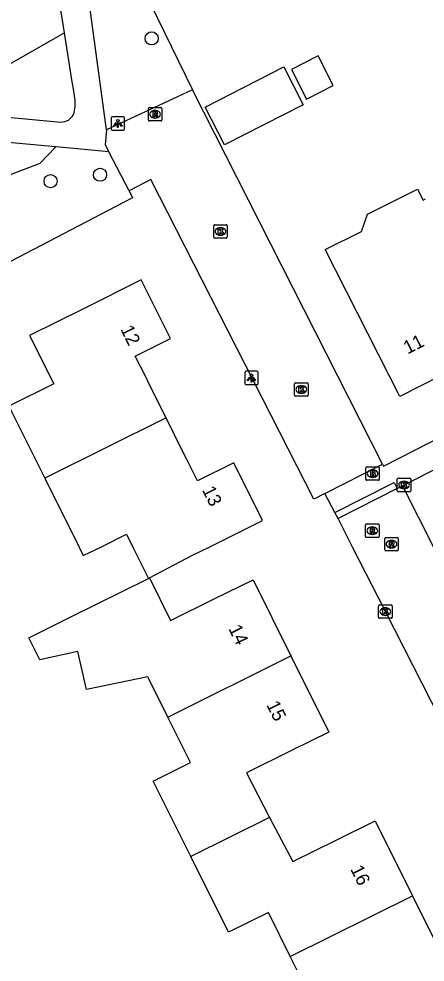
# Model space of a CAD drawing. Extents: x 162722 to 165099, y 384721 to 386283.
# Drawn here: x 163730.3 to 163760.6, y 384969 to 385039.4 of the extents above; entities that cross this region are included whole.
import ezdxf

# ---------------------------------------------------------------- set-up
doc = ezdxf.new("R2010")
doc.units = 0
for name, color, linetype in [('IMGEO_Boom', 7, 'Continuous'), ('IMGEO_Brandkraan', 7, 'Continuous'), ('IMGEO_Groenvoorziening', 7, 'Continuous'), ('IMGEO_Kolk', 7, 'Continuous'), ('IMGEO_Lichtpunt', 7, 'Continuous'), ('IMGEO_Pand', 7, 'Continuous'), ('IMGEO_Pand_nummerreeks', 7, 'Continuous'), ('IMGEO_Rijbaan_lokaal_open', 7, 'Continuous'), ('IMGEO_Rioolput', 7, 'Continuous'), ('IMGEO_Voetpad_open', 7, 'Continuous')]:
    doc.layers.add(name, color=color, linetype=linetype)

msp = doc.modelspace()

# ---------------------------------------------------------------- linework, layer by layer
at = {"layer": 'IMGEO_Boom'}
for centre in [(163740.246, 385037.942), (163736.396, 385027.77), (163732.709, 385027.289)]:
    msp.add_circle(centre, 0.489, dxfattribs=at)
at = {"layer": 'IMGEO_Brandkraan'}
for p, q in [((163756.215, 385005.051), (163756.215, 385005.903)), ((163756.29, 385005.977), (163757.142, 385005.977)), ((163756.703, 385005.757), (163756.728, 385005.757)), ((163757.216, 385005.903), (163757.216, 385005.051)), ((163757.142, 385004.977), (163756.29, 385004.977)), ((163756.726, 385005.197), (163756.701, 385005.197))]:
    msp.add_line(p, q, dxfattribs=at)
for points in [[(163756.215, 385005.051), (163756.215, 385005.903)], [(163756.29, 385005.977), (163757.142, 385005.977)], [(163756.563, 385005.677), (163756.563, 385005.277), (163756.776, 385005.277)], [(163756.794, 385005.677), (163756.563, 385005.677)], [(163757.216, 385005.903), (163757.216, 385005.051)], [(163757.142, 385004.977), (163756.29, 385004.977)], [(163756.742, 385005.596), (163756.688, 385005.596), (163756.688, 385005.52)], [(163756.688, 385005.52), (163756.741, 385005.52)], [(163756.75, 385005.444), (163756.688, 385005.444), (163756.688, 385005.363)], [(163756.688, 385005.363), (163756.75, 385005.363)]]:
    msp.add_lwpolyline(points, dxfattribs=at)
for centre, radius, start, end in [((163756.292, 385005.901), 0.0765, 91.55205, 178.44795), ((163756.292, 385005.901), 0.0765, 91.55205, 178.44795), ((163756.798, 385005.532), 0.145, 59.4692, 91.53667), ((163756.823, 385005.579), 0.0922, 285.51372, 58.15012), ((163757.14, 385005.901), 0.0765, 1.55205, 88.44795), ((163757.14, 385005.901), 0.0765, 1.55205, 88.44795), ((163756.292, 385005.053), 0.0765, 181.55205, 268.44795), ((163756.292, 385005.053), 0.0765, 181.55205, 268.44795), ((163756.743, 385005.558), 0.0379, 267.82845, 90.93552), ((163756.751, 385005.403), 0.0404, 269.87594, 90.50774), ((163756.782, 385005.528), 0.251, 268.66757, 293.53466), ((163756.828, 385005.387), 0.105, 301.31148, 78.98903), ((163757.14, 385005.053), 0.0765, 271.55205, 358.44795), ((163757.14, 385005.053), 0.0765, 271.55205, 358.44795)]:
    msp.add_arc(centre, radius, start, end, dxfattribs=at)
for centre, major_axis, ratio, start_param, end_param in [((163756.702, 385005.477), (-0.387, 0.002), 0.722429, 4.712389, 7.853982), ((163756.727, 385005.477), (-0.39, 0.002), 0.717154, 1.570796, 4.712389)]:
    msp.add_ellipse(centre, major_axis=major_axis, ratio=ratio, start_param=start_param, end_param=end_param, dxfattribs=at)
at = {"layer": 'IMGEO_Groenvoorziening'}
for points in [[(163738.045, 385044.879), (163743.285, 385034.094)], [(163733.752, 385038.348), (163723.683, 385032.609)], [(163715.637, 385026.452), (163717.423, 385023.192), (163721.071, 385022.027), (163726.195, 385024.046), (163728.214, 385027.228), (163731.94, 385028.626), (163733.096, 385029.842)], [(163738.567, 385026.557), (163738.822, 385026.058), (163738.155, 385025.71), (163714.087, 385013.147), (163707.49, 385026.219)]]:
    msp.add_lwpolyline(points, dxfattribs=at)
at = {"layer": 'IMGEO_Kolk'}
for p, q in [((163744.878, 385023.117), (163744.878, 385023.969)), ((163744.953, 385024.043), (163745.805, 385024.043)), ((163745.879, 385023.969), (163745.879, 385023.117)), ((163745.389, 385023.263), (163745.364, 385023.263)), ((163745.366, 385023.823), (163745.391, 385023.823)), ((163745.805, 385023.043), (163744.953, 385023.043)), ((163750.902, 385011.328), (163750.902, 385012.18)), ((163750.977, 385012.254), (163751.829, 385012.254)), ((163751.39, 385012.034), (163751.415, 385012.034)), ((163751.903, 385012.18), (163751.903, 385011.328)), ((163751.413, 385011.474), (163751.388, 385011.474)), ((163751.829, 385011.254), (163750.977, 385011.254)), ((163758.56, 385004.202), (163758.56, 385005.054)), ((163758.635, 385005.128), (163759.487, 385005.128)), ((163759.561, 385005.054), (163759.561, 385004.202)), ((163759.071, 385004.348), (163759.046, 385004.348)), ((163759.048, 385004.908), (163759.073, 385004.908)), ((163759.487, 385004.128), (163758.635, 385004.128)), ((163757.168, 384994.756), (163757.168, 384995.608)), ((163757.243, 384995.682), (163758.095, 384995.682)), ((163757.656, 384995.462), (163757.681, 384995.462)), ((163758.169, 384995.608), (163758.169, 384994.756)), ((163758.095, 384994.682), (163757.243, 384994.682)), ((163757.679, 384994.902), (163757.654, 384994.902))]:
    msp.add_line(p, q, dxfattribs=at)
for points in [[(163744.878, 385023.117), (163744.878, 385023.969)], [(163744.953, 385024.043), (163745.805, 385024.043)], [(163745.879, 385023.969), (163745.879, 385023.117)], [(163745.199, 385023.743), (163745.322, 385023.743), (163745.322, 385023.592), (163745.452, 385023.743), (163745.616, 385023.743), (163745.47, 385023.592), (163745.623, 385023.343), (163745.471, 385023.343), (163745.386, 385023.507), (163745.322, 385023.44), (163745.322, 385023.343), (163745.199, 385023.343), (163745.199, 385023.743)], [(163745.805, 385023.043), (163744.953, 385023.043)], [(163750.902, 385011.328), (163750.902, 385012.18)], [(163750.977, 385012.254), (163751.829, 385012.254)], [(163751.903, 385012.18), (163751.903, 385011.328)], [(163751.223, 385011.954), (163751.346, 385011.954), (163751.346, 385011.803), (163751.476, 385011.954), (163751.64, 385011.954), (163751.494, 385011.803), (163751.647, 385011.554), (163751.495, 385011.554), (163751.41, 385011.718), (163751.346, 385011.651), (163751.346, 385011.554), (163751.223, 385011.554), (163751.223, 385011.954)], [(163751.829, 385011.254), (163750.977, 385011.254)], [(163758.56, 385004.202), (163758.56, 385005.054)], [(163758.635, 385005.128), (163759.487, 385005.128)], [(163759.561, 385005.054), (163759.561, 385004.202)], [(163758.881, 385004.828), (163759.004, 385004.828), (163759.004, 385004.677), (163759.134, 385004.828), (163759.298, 385004.828), (163759.152, 385004.677), (163759.305, 385004.428), (163759.153, 385004.428), (163759.068, 385004.592), (163759.004, 385004.525), (163759.004, 385004.428), (163758.881, 385004.428), (163758.881, 385004.828)], [(163759.487, 385004.128), (163758.635, 385004.128)], [(163757.168, 384994.756), (163757.168, 384995.608)], [(163757.243, 384995.682), (163758.095, 384995.682)], [(163757.489, 384995.382), (163757.612, 384995.382), (163757.612, 384995.231), (163757.742, 384995.382), (163757.906, 384995.382), (163757.76, 384995.231), (163757.913, 384994.982), (163757.761, 384994.982), (163757.676, 384995.146), (163757.612, 384995.079), (163757.612, 384994.982), (163757.489, 384994.982), (163757.489, 384995.382)], [(163758.169, 384995.608), (163758.169, 384994.756)], [(163758.095, 384994.682), (163757.243, 384994.682)]]:
    msp.add_lwpolyline(points, dxfattribs=at)
for centre, start, end in [((163744.955, 385023.967), 91.55205, 178.44795), ((163744.955, 385023.967), 91.55205, 178.44795), ((163745.803, 385023.967), 1.55205, 88.44795), ((163745.803, 385023.967), 1.55205, 88.44795), ((163744.955, 385023.119), 181.55205, 268.44795), ((163744.955, 385023.119), 181.55205, 268.44795), ((163745.803, 385023.119), 271.55205, 358.44795), ((163745.803, 385023.119), 271.55205, 358.44795), ((163750.979, 385012.178), 91.55205, 178.44795), ((163750.979, 385012.178), 91.55205, 178.44795), ((163751.827, 385012.178), 1.55205, 88.44795), ((163751.827, 385012.178), 1.55205, 88.44795), ((163750.979, 385011.33), 181.55205, 268.44795), ((163750.979, 385011.33), 181.55205, 268.44795), ((163751.827, 385011.33), 271.55205, 358.44795), ((163751.827, 385011.33), 271.55205, 358.44795), ((163758.637, 385005.052), 91.55205, 178.44795), ((163758.637, 385005.052), 91.55205, 178.44795), ((163759.485, 385005.052), 1.55205, 88.44795), ((163759.485, 385005.052), 1.55205, 88.44795), ((163758.637, 385004.204), 181.55205, 268.44795), ((163758.637, 385004.204), 181.55205, 268.44795), ((163759.485, 385004.204), 271.55205, 358.44795), ((163759.485, 385004.204), 271.55205, 358.44795), ((163757.245, 384995.606), 91.55205, 178.44795), ((163757.245, 384995.606), 91.55205, 178.44795), ((163758.093, 384995.606), 1.55205, 88.44795), ((163758.093, 384995.606), 1.55205, 88.44795), ((163757.245, 384994.758), 181.55205, 268.44795), ((163757.245, 384994.758), 181.55205, 268.44795), ((163758.093, 384994.758), 271.55205, 358.44795), ((163758.093, 384994.758), 271.55205, 358.44795)]:
    msp.add_arc(centre, 0.0765, start, end, dxfattribs=at)
for centre, major_axis, ratio, start_param, end_param in [((163745.365, 385023.543), (-0.387, 0.002), 0.722429, 4.712389, 7.853982), ((163745.39, 385023.543), (-0.39, 0.002), 0.717154, 1.570796, 4.712389), ((163751.389, 385011.754), (-0.387, 0.002), 0.722429, 4.712389, 7.853982), ((163751.414, 385011.754), (-0.39, 0.002), 0.717154, 1.570796, 4.712389), ((163759.047, 385004.628), (-0.387, 0.002), 0.722429, 4.712389, 7.853982), ((163759.072, 385004.628), (-0.39, 0.002), 0.717154, 1.570796, 4.712389), ((163757.655, 384995.182), (-0.387, 0.002), 0.722429, 4.712389, 7.853982), ((163757.68, 384995.182), (-0.39, 0.002), 0.717154, 1.570796, 4.712389)]:
    msp.add_ellipse(centre, major_axis=major_axis, ratio=ratio, start_param=start_param, end_param=end_param, dxfattribs=at)
at = {"layer": 'IMGEO_Lichtpunt'}
for p, q in [((163737.232, 385032.001), (163737.232, 385031.194)), ((163737.232, 385032.001), (163737.232, 385031.194)), ((163738.134, 385032.096), (163737.326, 385032.096)), ((163738.134, 385032.096), (163737.326, 385032.096)), ((163738.228, 385031.194), (163738.228, 385032.001)), ((163738.228, 385031.194), (163738.228, 385032.001)), ((163737.326, 385031.1), (163738.134, 385031.1)), ((163737.326, 385031.1), (163738.134, 385031.1)), ((163747.182, 385013.012), (163747.182, 385012.205)), ((163747.182, 385013.012), (163747.182, 385012.205)), ((163748.084, 385013.107), (163747.276, 385013.107)), ((163748.084, 385013.107), (163747.276, 385013.107)), ((163748.178, 385012.205), (163748.178, 385013.012)), ((163748.178, 385012.205), (163748.178, 385013.012)), ((163747.276, 385012.111), (163748.084, 385012.111)), ((163747.276, 385012.111), (163748.084, 385012.111))]:
    msp.add_line(p, q, dxfattribs=at)
for points in [[(163737.606, 385031.665), (163737.645, 385031.637), (163737.457, 385031.375), (163737.419, 385031.402), (163737.606, 385031.665)], [(163737.708, 385031.617), (163737.755, 385031.617), (163737.755, 385031.295), (163737.708, 385031.295), (163737.708, 385031.617)], [(163737.818, 385031.637), (163737.856, 385031.664), (163738.043, 385031.402), (163738.004, 385031.374), (163737.818, 385031.637)], [(163747.556, 385012.676), (163747.595, 385012.648), (163747.407, 385012.386), (163747.369, 385012.413), (163747.556, 385012.676)], [(163747.658, 385012.628), (163747.705, 385012.628), (163747.705, 385012.306), (163747.658, 385012.306), (163747.658, 385012.628)], [(163747.768, 385012.648), (163747.806, 385012.675), (163747.993, 385012.413), (163747.954, 385012.385), (163747.768, 385012.648)]]:
    msp.add_lwpolyline(points, dxfattribs=at)
for centre in [(163737.731, 385031.799), (163747.681, 385012.81)]:
    msp.add_circle(centre, 0.0994, dxfattribs=at)
for centre, start, end in [((163737.326, 385032.001), 90, 180), ((163737.326, 385032.001), 90, 180), ((163738.134, 385032.001), 0, 90), ((163738.134, 385032.001), 0, 90), ((163737.326, 385031.194), 180, 270), ((163737.326, 385031.194), 180, 270), ((163738.134, 385031.194), 270, 0), ((163738.134, 385031.194), 270, 360), ((163747.276, 385013.012), 90, 180), ((163747.276, 385013.012), 90, 180), ((163748.084, 385013.012), 0, 90), ((163748.084, 385013.012), 0, 90), ((163747.276, 385012.205), 180, 270), ((163747.276, 385012.205), 180, 270), ((163748.084, 385012.205), 270, 0), ((163748.084, 385012.205), 270, 360)]:
    msp.add_arc(centre, 0.0946, start, end, dxfattribs=at)
at = {"layer": 'IMGEO_Pand'}
for points in [[(163750.668, 385035.611), (163751.798, 385033.404), (163753.784, 385034.421), (163752.654, 385036.628), (163750.668, 385035.611)], [(163751.537, 385032.996), (163745.671, 385029.993), (163744.223, 385032.821), (163750.089, 385035.824), (163751.537, 385032.996)], [(163765.26, 385016.849), (163762.37, 385015.385), (163763.301, 385013.546), (163758.739, 385011.235), (163753.192, 385022.186), (163755.881, 385023.548), (163756.343, 385024.825), (163760.057, 385026.705), (163760.482, 385025.866), (163760.67, 385025.961)], [(163741.316, 385009.636), (163740.111, 385012.059), (163739.801, 385012.683), (163739.025, 385014.244), (163741.647, 385015.547), (163739.47, 385019.924), (163735.204, 385017.803), (163731.149, 385015.787), (163732.948, 385012.168), (163729.604, 385010.506), (163732.271, 385005.142)], [(163741.316, 385009.636), (163732.271, 385005.142)], [(163740.074, 384997.693), (163743.289, 384999.383), (163744.53, 385000), (163748.517, 385001.983), (163746.376, 385006.29), (163743.653, 385004.936), (163742.832, 385006.587), (163742.577, 385007.101), (163741.316, 385009.636)], [(163732.271, 385005.142), (163734.828, 385000), (163735.148, 384999.356), (163736.444, 385000), (163738.374, 385000.96), (163738.852, 385000), (163740.014, 384997.662)], [(163741.448, 384987.316), (163740.024, 384990.18), (163739.961, 384990.306), (163735.388, 384989.361), (163734.734, 384992.209), (163731.909, 384991.592), (163731.095, 384993.229), (163734.168, 384994.756), (163740.014, 384997.662)], [(163740.014, 384997.662), (163740.074, 384997.693)], [(163740.074, 384997.693), (163741.658, 384994.507), (163744.91, 384996.124), (163747.8, 384997.561), (163750.625, 384991.88)], [(163741.448, 384987.316), (163750.625, 384991.88)], [(163750.625, 384991.88), (163753.45, 384986.198), (163750.717, 384984.839), (163747.308, 384983.144), (163749.036, 384979.836)], [(163743.164, 384976.913), (163740.366, 384982.54), (163743.137, 384983.918), (163741.448, 384987.316)], [(163749.036, 384979.836), (163743.164, 384976.913)], [(163749.036, 384979.836), (163750.763, 384976.531), (163754.038, 384978.16), (163756.905, 384979.586), (163759.69, 384973.984)], [(163750.581, 384969.45), (163748.947, 384972.736), (163745.975, 384971.259), (163743.164, 384976.913)], [(163759.69, 384973.984), (163761.287, 384970.773), (163761.856, 384969.629), (163764.958, 384970.319), (163766.926, 384966.361), (163758.55, 384962.196), (163759.265, 384960.758), (163755.768, 384959.019), (163753.371, 384963.839), (163751.144, 384968.317), (163750.581, 384969.45)], [(163750.581, 384969.45), (163759.69, 384973.984)]]:
    msp.add_lwpolyline(points, dxfattribs=at)
at = {"layer": 'IMGEO_Rijbaan_lokaal_open'}
for points in [[(163743.285, 385034.094), (163736.866, 385031.109)], [(163757.459, 385006.177), (163743.285, 385034.094)], [(163736.866, 385031.109), (163736.787, 385030.008), (163737.06, 385029.479)], [(163738.567, 385026.557), (163737.06, 385029.479)], [(163753.157, 385003.995), (163752.338, 385003.569), (163740.176, 385027.426), (163738.567, 385026.557)], [(163758.942, 385004.57), (163768.327, 385009.356), (163768.724, 385009.555)], [(163753.157, 385003.995), (163757.459, 385006.177)], [(163758.54, 385004.374), (163754.144, 385002.139)], [(163758.54, 385004.374), (163758.942, 385004.57)], [(163758.942, 385004.57), (163762.509, 384997.523)], [(163773.45, 384964.172), (163757.669, 384995.182), (163755.228, 385000), (163754.144, 385002.139)]]:
    msp.add_lwpolyline(points, dxfattribs=at)
at = {"layer": 'IMGEO_Rioolput'}
for p, q in [((163739.997, 385031.854), (163739.997, 385032.706)), ((163740.072, 385032.78), (163740.924, 385032.78)), ((163740.485, 385032.56), (163740.51, 385032.56)), ((163740.998, 385032.706), (163740.998, 385031.854)), ((163740.924, 385031.78), (163740.072, 385031.78)), ((163740.508, 385032), (163740.483, 385032)), ((163756.194, 385000.792), (163756.194, 385001.644)), ((163756.269, 385001.718), (163757.121, 385001.718)), ((163756.682, 385001.498), (163756.707, 385001.498)), ((163757.195, 385001.644), (163757.195, 385000.792)), ((163756.705, 385000.938), (163756.68, 385000.938)), ((163757.121, 385000.718), (163756.269, 385000.718)), ((163757.624, 384999.793), (163757.624, 385000.645)), ((163757.699, 385000.719), (163758.551, 385000.719)), ((163758.112, 385000.499), (163758.137, 385000.499)), ((163758.625, 385000.645), (163758.625, 384999.793)), ((163758.551, 384999.719), (163757.699, 384999.719)), ((163758.135, 384999.939), (163758.11, 384999.939))]:
    msp.add_line(p, q, dxfattribs=at)
for points in [[(163739.997, 385031.854), (163739.997, 385032.706)], [(163740.072, 385032.78), (163740.924, 385032.78)], [(163740.586, 385032.478), (163740.334, 385032.48), (163740.334, 385032.08)], [(163740.512, 385032.399), (163740.458, 385032.399), (163740.458, 385032.318)], [(163740.998, 385032.706), (163740.998, 385031.854)], [(163740.924, 385031.78), (163740.072, 385031.78)], [(163740.334, 385032.08), (163740.458, 385032.08), (163740.458, 385032.242), (163740.469, 385032.242)], [(163740.458, 385032.318), (163740.51, 385032.318)], [(163740.516, 385032.213), (163740.587, 385032.08), (163740.727, 385032.08), (163740.662, 385032.206)], [(163756.194, 385000.792), (163756.194, 385001.644)], [(163756.269, 385001.718), (163757.121, 385001.718)], [(163757.195, 385001.644), (163757.195, 385000.792)], [(163756.783, 385001.416), (163756.531, 385001.418), (163756.531, 385001.018)], [(163756.531, 385001.018), (163756.655, 385001.018), (163756.655, 385001.18), (163756.666, 385001.18)], [(163756.709, 385001.337), (163756.655, 385001.337), (163756.655, 385001.256)], [(163756.655, 385001.256), (163756.707, 385001.256)], [(163756.713, 385001.151), (163756.784, 385001.018), (163756.924, 385001.018), (163756.859, 385001.144)], [(163757.121, 385000.718), (163756.269, 385000.718)], [(163757.624, 384999.793), (163757.624, 385000.645)], [(163757.699, 385000.719), (163758.551, 385000.719)], [(163758.213, 385000.417), (163757.961, 385000.419), (163757.961, 385000.019)], [(163757.961, 385000.019), (163758.085, 385000.019), (163758.085, 385000.181), (163758.096, 385000.181)], [(163758.139, 385000.338), (163758.085, 385000.338), (163758.085, 385000.257)], [(163758.085, 385000.257), (163758.137, 385000.257)], [(163758.143, 385000.152), (163758.214, 385000.019), (163758.354, 385000.019), (163758.289, 385000.145)], [(163758.625, 385000.645), (163758.625, 384999.793)], [(163758.551, 384999.719), (163757.699, 384999.719)]]:
    msp.add_lwpolyline(points, dxfattribs=at)
for centre, radius, start, end in [((163740.074, 385032.704), 0.0765, 91.55205, 178.44795), ((163740.074, 385032.704), 0.0765, 91.55205, 178.44795), ((163740.518, 385032.303), 0.0964, 77.00612, 93.18647), ((163740.532, 385032.36), 0.0378, 276.66336, 79.67722), ((163740.585, 385032.368), 0.109, 350.36119, 89.41601), ((163740.922, 385032.704), 0.0765, 1.55205, 88.44795), ((163740.922, 385032.704), 0.0765, 1.55205, 88.44795), ((163740.074, 385031.856), 0.0765, 181.55205, 268.44795), ((163740.074, 385031.856), 0.0765, 181.55205, 268.44795), ((163740.468, 385032.189), 0.0533, 26.02933, 88.69889), ((163740.494, 385032.507), 0.19, 274.7715, 282.96867), ((163740.583, 385032.368), 0.112, 277.58423, 350.98172), ((163740.567, 385032.153), 0.108, 29.51342, 73.79051), ((163740.922, 385031.856), 0.0765, 271.55205, 358.44795), ((163740.922, 385031.856), 0.0765, 271.55205, 358.44795), ((163756.271, 385001.642), 0.0765, 91.55205, 178.44795), ((163756.271, 385001.642), 0.0765, 91.55205, 178.44795), ((163757.119, 385001.642), 0.0765, 1.55205, 88.44795), ((163757.119, 385001.642), 0.0765, 1.55205, 88.44795), ((163756.271, 385000.794), 0.0765, 181.55205, 268.44795), ((163756.271, 385000.794), 0.0765, 181.55205, 268.44795), ((163756.665, 385001.127), 0.0533, 26.02933, 88.69889), ((163756.691, 385001.445), 0.19, 274.7715, 282.96867), ((163756.715, 385001.241), 0.0964, 77.00612, 93.18647), ((163756.729, 385001.298), 0.0378, 276.66336, 79.67722), ((163756.782, 385001.306), 0.109, 350.36119, 89.41601), ((163756.78, 385001.306), 0.112, 277.58423, 350.98172), ((163756.764, 385001.091), 0.108, 29.51342, 73.79051), ((163757.119, 385000.794), 0.0765, 271.55205, 358.44795), ((163757.119, 385000.794), 0.0765, 271.55205, 358.44795), ((163757.701, 385000.643), 0.0765, 91.55205, 178.44795), ((163757.701, 385000.643), 0.0765, 91.55205, 178.44795), ((163758.095, 385000.128), 0.0533, 26.02933, 88.69889), ((163758.121, 385000.446), 0.19, 274.7715, 282.96867), ((163758.145, 385000.242), 0.0964, 77.00612, 93.18647), ((163758.159, 385000.299), 0.0378, 276.66336, 79.67722), ((163758.212, 385000.307), 0.109, 350.36119, 89.41601), ((163758.21, 385000.307), 0.112, 277.58423, 350.98172), ((163758.194, 385000.092), 0.108, 29.51342, 73.79051), ((163758.549, 385000.643), 0.0765, 1.55205, 88.44795), ((163758.549, 385000.643), 0.0765, 1.55205, 88.44795), ((163757.701, 384999.795), 0.0765, 181.55205, 268.44795), ((163757.701, 384999.795), 0.0765, 181.55205, 268.44795), ((163758.549, 384999.795), 0.0765, 271.55205, 358.44795), ((163758.549, 384999.795), 0.0765, 271.55205, 358.44795)]:
    msp.add_arc(centre, radius, start, end, dxfattribs=at)
for centre, major_axis, ratio, start_param, end_param in [((163740.484, 385032.28), (-0.387, 0.002), 0.722429, 4.712389, 7.853982), ((163740.509, 385032.28), (-0.39, 0.002), 0.717154, 1.570796, 4.712389), ((163756.681, 385001.218), (-0.387, 0.002), 0.722429, 4.712389, 7.853982), ((163756.706, 385001.218), (-0.39, 0.002), 0.717154, 1.570796, 4.712389), ((163758.111, 385000.219), (-0.387, 0.002), 0.722429, 4.712389, 7.853982), ((163758.136, 385000.219), (-0.39, 0.002), 0.717154, 1.570796, 4.712389)]:
    msp.add_ellipse(centre, major_axis=major_axis, ratio=ratio, start_param=start_param, end_param=end_param, dxfattribs=at)
at = {"layer": 'IMGEO_Voetpad_open'}
for points in [[(163736.866, 385031.109), (163735.313, 385042.695), (163734.975, 385044.596), (163734.441, 385046.451), (163733.716, 385048.241), (163732.602, 385050.277)], [(163733.752, 385038.348), (163733.034, 385042.907), (163732.409, 385046.872), (163731.143, 385049.533)], [(163734.525, 385033.481), (163734.386, 385034.331), (163734.329, 385034.689), (163733.752, 385038.348)], [(163723.683, 385032.609), (163733.478, 385031.697)], [(163733.096, 385029.842), (163721.576, 385030.897)], [(163737.06, 385029.479), (163733.096, 385029.842)], [(163757.459, 385006.177), (163757.517, 385006.039), (163767.841, 385011.304)], [(163753.91, 385002.58), (163758.314, 385004.819), (163758.54, 385004.374)], [(163753.91, 385002.58), (163753.157, 385003.995)], [(163754.144, 385002.139), (163753.91, 385002.58)]]:
    msp.add_lwpolyline(points, dxfattribs=at)
for centre, radius, start, end in [((163731.739, 385033.129), 2.808, 342.28123, 7.21008), ((163733.508, 385032.697), 1, 268.30685, 334.99691)]:
    msp.add_arc(centre, radius, start, end, dxfattribs=at)

# ---------------------------------------------------------------- texts
at = {"layer": 'IMGEO_Pand_nummerreeks'}
for s, rotation, p in [('12', 296.44179, (163737.892, 385016.261)), ('11', 26.86568, (163759.326, 385014.357)), ('13', 296.43606, (163743.981, 385004.265)), ('14', 296.43606, (163745.948, 384993.919)), ('15', 296.43784, (163748.773, 384988.237)), ('16', 296.43399, (163755.033, 384975.983))]:
    msp.add_text(s, height=1, rotation=rotation, dxfattribs=at).set_placement(p)

doc.saveas('drawing.dxf')
